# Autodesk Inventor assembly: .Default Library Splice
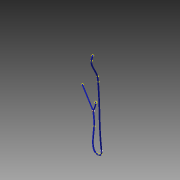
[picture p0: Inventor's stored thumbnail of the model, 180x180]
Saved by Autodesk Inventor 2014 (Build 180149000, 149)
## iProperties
Part Number: .Default Library Splice
Material: Default
Description: Default Library Splice
ParentFileIdentifier: 5|1|0|0|108|1|0|0|80|0|65|0|84|0|72|0|83|0|59|0|67|0|58|0|92|0|86|0|97|0|117|0|108|0|116|0|32|0|87|0|111|0|114|0|107|0|115|0|112|0|97|0|99|0|101|0|92|0|69|0|110
Created: 2009-02
Part Number: 100500.Harness1
Document SubType Name: Assembly
Designer: Autodesk
HarnessSettings: <HarnessSettings><Defaults><Segments><Diameter value="0.200 in" fromwires="True"/><Offset value="0.100 in"/><ColorStyle value="Blue"/><RoundUp value=""/><BendRa
Author: Autodesk
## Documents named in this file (2)
- C:\Users\iTools\Desktop\tutorial files\Automotive\1000\100500\100500.Harness1.iam
- C:\Users\iTools\Desktop\tutorial files\Automotive\1000\100500\100500.Harness1.ipt
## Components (2 placed, 2 different names)
1. Harness1
2. HA_VC_141:1
